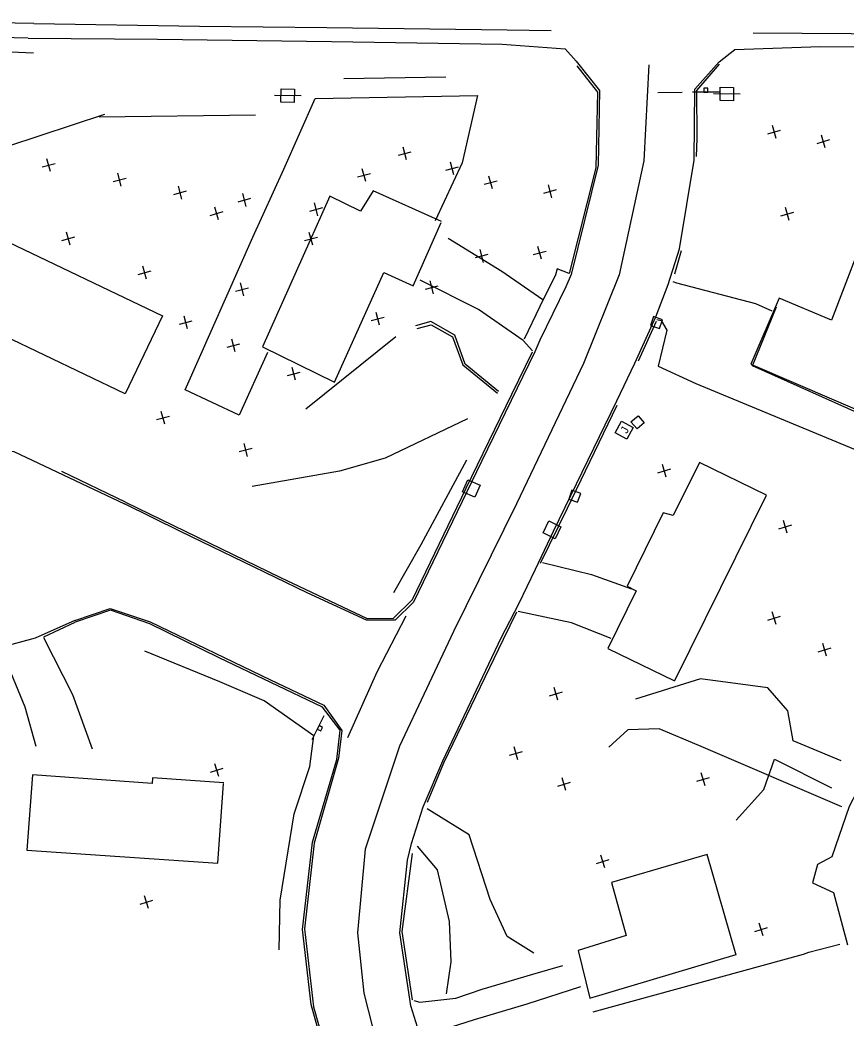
# Model space of a CAD drawing. Extents: x 4711259 to 4716401, y 890074 to 892728.
# Drawn here: x 4713612.2 to 4713922, y 890972 to 891346.1 of the extents above; entities that cross this region are included whole.
import ezdxf

# ---------------------------------------------------------------- set-up
doc = ezdxf.new("R2010")
doc.units = 0
for name, color, linetype in [('E_HY_STORM_Inlet', 7, 'Continuous'), ('E_RDWY_PHOTOG_Eave', 7, 'Continuous'), ('E_RDWY_PHOTOG_Fence', 7, 'Continuous'), ('E_RDWY_ROAD_Approach', 7, 'Continuous'), ('E_RDWY_ROAD_Curb', 7, 'Continuous'), ('E_RDWY_ROAD_EdgeAsph', 7, 'Continuous'), ('E_RDWY_ROAD_EdgeGravel', 7, 'Continuous'), ('E_RDWY_ROAD_Mailbox', 7, 'Continuous'), ('E_RDWY_ROAD_Sidewalk', 7, 'Continuous'), ('E_RDWY_ROAD_Striping', 7, 'Continuous'), ('E_RDWY_ROAD_TBofCurb', 7, 'Continuous'), ('E_TERR_DTM_BrkLines', 7, 'Continuous'), ('E_TERR_DTM_RandomPt', 7, 'Continuous'), ('E_TRAF_SIGN_PublicSign', 7, 'Continuous'), ('E_UTIL_COMM_General', 7, 'Continuous'), ('E_UTIL_ELEC_GENERAL', 7, 'Continuous'), ('E_UTIL_ELEC_POLE', 7, 'Continuous')]:
    doc.layers.add(name, color=color, linetype=linetype)

msp = doc.modelspace()

# ---------------------------------------------------------------- linework, layer by layer
at = {"layer": 'E_HY_STORM_Inlet'}
for p, q in [((4713781.5, 891170.44), (4713781.5, 891170.44)), ((4713811.71, 891154.94), (4713811.71, 891154.94))]:
    msp.add_line(p, q, dxfattribs=at)
for points in [[(4713784.8, 891171.73), (4713782.79, 891167.15), (4713778.21, 891169.16), (4713780.22, 891173.74)], [(4713815.05, 891156.09), (4713812.86, 891151.6), (4713808.37, 891153.79), (4713810.56, 891158.28)]]:
    msp.add_lwpolyline(points, close=True, dxfattribs=at)
at = {"layer": 'E_RDWY_PHOTOG_Eave'}
for points in [[(4713770.26, 891270.48), (4713744.67, 891282.04), (4713739.98, 891274.39), (4713728.39, 891280.01), (4713703.14, 891223.52), (4713730.13, 891210.37), (4713748.66, 891251.38), (4713759.64, 891246.46), (4713770.2, 891270.2)], [(4713934.33, 891196.53), (4713960.95, 891259.55), (4713931.47, 891272.28), (4713916.57, 891233.61), (4713896.9, 891241.74), (4713886.26, 891217.06), (4713934.29, 891196.47)], [(4713857.75, 891098.46), (4713892.22, 891167.97), (4713867.04, 891180.17), (4713857.2, 891160.28), (4713853.47, 891161.32), (4713839.9, 891133.88), (4713843.25, 891132.13), (4713832.68, 891110.45), (4713857.61, 891098.37)], [(4713688.73, 891060.1), (4713661.94, 891061.99), (4713661.79, 891059.93), (4713616.92, 891063.17), (4713614.83, 891034.87), (4713686.4, 891029.98), (4713688.58, 891059.91)], [(4713880.83, 890995.6), (4713869.91, 891033.23), (4713834, 891022.8), (4713839.58, 891002.9), (4713821.55, 890997.33), (4713825.88, 890979.41), (4713880.76, 890995.83)]]:
    msp.add_lwpolyline(points, dxfattribs=at)
msp.add_lwpolyline([(4713651.67, 891205.9), (4713591.05, 891234.94), (4713605.06, 891264.19), (4713665.68, 891235.14)], close=True, dxfattribs=at)
at = {"layer": 'E_RDWY_PHOTOG_Fence'}
for points in [[(4713705.08, 891221.42), (4713694.43, 891197.99), (4713674.22, 891207.45), (4713699.58, 891264.71), (4713711.22, 891290.12), (4713722.98, 891316.63), (4713783.79, 891317.77), (4713778.07, 891292.53), (4713767.89, 891270.76)], [(4713920.39, 891051.18), (4713866.81, 891074.09), (4713851.95, 891080.37), (4713840.15, 891079.97), (4713833.04, 891073.53)], [(4713827.17, 890974.29), (4713905.99, 890995.98), (4713908.03, 890996.62), (4713919.65, 890999.64)]]:
    msp.add_lwpolyline(points, dxfattribs=at)
at = {"layer": 'E_RDWY_ROAD_Approach'}
for points in [[(4713772.8, 891264.33), (4713792.93, 891251.96), (4713808.27, 891241.25)], [(4713804.47, 891222.03), (4713800.9, 891225.9), (4713784.12, 891237.6), (4713762.35, 891248.54)], [(4713857.1, 891248.08), (4713858.4, 891247.54), (4713888.03, 891239.82), (4713894.19, 891237.03)], [(4713931.07, 891196.74), (4713886.94, 891216.45), (4713895.86, 891238.55)], [(4713851.09, 891233.83), (4713852.72, 891233.38), (4713854.79, 891229.83), (4713851.5, 891216.25), (4713865.66, 891209.81), (4713926.93, 891184.43), (4713931.12, 891196.58)], [(4713808.18, 891142.66), (4713826.51, 891138.25), (4713841.53, 891132.9)], [(4713833.91, 891114.29), (4713819.02, 891120.17), (4713799.03, 891124.38)], [(4713639.4, 891072.75), (4713632.04, 891093.18), (4713621.12, 891114.5)], [(4713605.32, 891109.86), (4713614.07, 891088.61), (4713618.17, 891073.87)], [(4713759.91, 890978.62), (4713762.11, 890977.91), (4713775.66, 890979.49), (4713785.53, 890982.83), (4713804.53, 890988.41), (4713815.85, 890991.69)], [(4713822.42, 890983.73), (4713802.31, 890977.23), (4713782.55, 890971.3), (4713764.93, 890965.71), (4713763.33, 890965.14)]]:
    msp.add_lwpolyline(points, dxfattribs=at)
at = {"layer": 'E_RDWY_ROAD_Curb'}
for points in [[(4713820.79, 891330.56), (4713829.53, 891319.64), (4713829.1, 891291.65), (4713818.97, 891250.72), (4713816.95, 891246.05), (4713807.22, 891226.01), (4713805.31, 891221.73), (4713785.27, 891180.53)], [(4713812.27, 891154.47), (4713836.08, 891203.37), (4713842.74, 891217.43), (4713850.72, 891234.74), (4713855.24, 891246.87), (4713859.57, 891260.23), (4713865.04, 891293.48), (4713865.31, 891320.17), (4713874.37, 891330.31)], [(4713632.75, 891120.93), (4713617.97, 891114.35), (4713604.44, 891110.69), (4713587.66, 891112.51), (4713571.64, 891123.24), (4713563.52, 891138.46), (4713562.44, 891152.56), (4713565.42, 891163.76), (4713583.14, 891182.06), (4713594.75, 891185.87), (4713609.88, 891184.34), (4713651.39, 891164.73)], [(4713785.27, 891180.53), (4713759.74, 891127.86), (4713752.88, 891121.11), (4713742.14, 891121.05), (4713719.98, 891131.41), (4713672.44, 891154.33), (4713651.39, 891164.73)], [(4713792.72, 891114.44), (4713799.23, 891127.29), (4713805.52, 891140.25), (4713812.27, 891154.47)], [(4713632.75, 891120.93), (4713646.08, 891125.51), (4713661.04, 891120.52), (4713706.14, 891098.8), (4713726.12, 891089.24), (4713732.92, 891079.81), (4713731.68, 891069.33), (4713722.58, 891037.56), (4713718.87, 891005.38), (4713722.24, 890976.18), (4713729.82, 890949.71), (4713731.63, 890945.49), (4713739.82, 890925.16), (4713753.37, 890890.9), (4713766.39, 890858.38), (4713785.05, 890820.46), (4713795.01, 890806.04)], [(4713819.53, 890832.89), (4713799.04, 890872.21), (4713798.23, 890874.51), (4713792.3, 890889.41), (4713775.49, 890931.67), (4713766.89, 890952.83), (4713762.59, 890964.52), (4713758.84, 890976.58), (4713754.63, 891003.97), (4713757.58, 891031.15), (4713759.06, 891037.39), (4713763.46, 891051.1), (4713770.75, 891068.43), (4713792.72, 891114.44)]]:
    msp.add_lwpolyline(points, dxfattribs=at)
at = {"layer": 'E_RDWY_ROAD_EdgeAsph'}
for points in [[(4713615.36, 891339.27), (4713551.94, 891340.74), (4713493.65, 891341.6), (4713437.61, 891342.74), (4713435.93, 891340.25), (4713420.8, 891342.23), (4713393.99, 891341.13), (4713355.17, 891338.55), (4713296.95, 891336.37), (4713247.9, 891334.38)], [(4713615.36, 891339.27), (4713663.82, 891338.83), (4713729.08, 891337.94), (4713793.1, 891337.01), (4713816.66, 891335.3), (4713820.79, 891330.56)], [(4713874.37, 891330.31), (4713880.32, 891335.02), (4713912.29, 891336.09), (4713970.87, 891335.69), (4714017.26, 891335.57), (4714062.02, 891335.32), (4714103.97, 891334.6)]]:
    msp.add_lwpolyline(points, dxfattribs=at)
at = {"layer": 'E_RDWY_ROAD_EdgeGravel'}
for points in [[(4713804.86, 890996.32), (4713794.95, 891002.56), (4713788.54, 891016.43), (4713780.64, 891040.67), (4713764.89, 891050.43)], [(4713761.2, 891036.38), (4713768.63, 891027.54), (4713773.13, 891008.13), (4713773.85, 890993.05), (4713772.01, 890981.05)]]:
    msp.add_lwpolyline(points, dxfattribs=at)
at = {"layer": 'E_RDWY_ROAD_Mailbox'}
for points in [[(4713848.68, 891231.56), (4713851.98, 891230.4), (4713853.14, 891233.7), (4713849.84, 891234.86)], [(4713818.03, 891166.47), (4713821.33, 891165.31), (4713822.49, 891168.61), (4713819.19, 891169.77)]]:
    msp.add_lwpolyline(points, close=True, dxfattribs=at)
at = {"layer": 'E_RDWY_ROAD_Sidewalk'}
msp.add_lwpolyline([(4713818.2, 891251.03), (4713813.7, 891252.73), (4713813, 891250.57), (4713807.2, 891238.7), (4713801.27, 891226.37)], dxfattribs=at)
at = {"layer": 'E_RDWY_ROAD_Striping'}
for points in [[(4713617.48, 891344.68), (4713540.79, 891346.06), (4713469.69, 891346.85), (4713449.38, 891346.86)], [(4713617.48, 891344.68), (4713679.52, 891343.72), (4713727.32, 891343.2), (4713794.97, 891342.38), (4713811.47, 891342.13)], [(4713887.16, 891341.3), (4713942.27, 891340.9), (4714001.89, 891340.83), (4714065.08, 891340.32), (4714120.8, 891339.62), (4714182.86, 891338.54), (4714241.54, 891338.23), (4714273.17, 891337.79)], [(4713848.1, 891329.22), (4713846.22, 891293.23), (4713836.95, 891250.59), (4713823.5, 891217.31), (4713798.38, 891164.65), (4713774.76, 891116.85)], [(4713860.6, 891318.87), (4713851.43, 891318.73)], [(4713754.59, 891073.85), (4713741.63, 891035.28), (4713738.8, 891003.98), (4713741.22, 890981.26), (4713749.08, 890950.43), (4713760.83, 890918.14), (4713781.36, 890868.24), (4713801.22, 890831.56)]]:
    msp.add_lwpolyline(points, dxfattribs=at)
at = {"layer": 'E_RDWY_ROAD_TBofCurb'}
for points in [[(4713818.33, 891251.01), (4713828.33, 891290.58), (4713828.96, 891319.01), (4713821.11, 891328.93)], [(4713874.45, 891329.47), (4713865.91, 891319.59), (4713866.09, 891301.65), (4713865.8, 891294.89)], [(4713860.18, 891259.54), (4713857.71, 891250.79)], [(4713850.74, 891233.1), (4713844.03, 891218.19)], [(4713651.83, 891165.39), (4713709.88, 891137.1), (4713742.4, 891121.77), (4713752.24, 891121.88), (4713759.42, 891128.81), (4713779.6, 891170.56), (4713796.72, 891205.79), (4713804.45, 891221.64)], [(4713836.01, 891201.56), (4713817.38, 891162.91), (4713807.23, 891142.32)], [(4713651.83, 891165.39), (4713627.89, 891176.89)], [(4713729.1, 890949.56), (4713721.38, 890977.01), (4713718.2, 891005.13), (4713721.93, 891037.92), (4713731.01, 891068.92), (4713732.3, 891079.84), (4713725.62, 891088.56), (4713686.9, 891107.05), (4713660.94, 891119.71), (4713646.23, 891124.8), (4713632.95, 891120.39)], [(4713798.44, 891124.11), (4713793.44, 891113.85)], [(4713621.22, 891114.92), (4713632.95, 891120.39)], [(4713793.44, 891113.85), (4713771.07, 891067.56), (4713764.96, 891052.75)], [(4713759.31, 891033.64), (4713755.48, 891004.36), (4713759.27, 890978.78)]]:
    msp.add_lwpolyline(points, dxfattribs=at)
at = {"layer": 'E_TERR_DTM_BrkLines'}
for points in [[(4713302.13, 890810.84), (4713317.61, 890862.47), (4713325.92, 890904.14), (4713338.96, 890949.45), (4713350.11, 890993.6), (4713363.4, 891040.76), (4713373.13, 891091.88), (4713385.24, 891139.46), (4713397.2, 891188.39), (4713412.55, 891244.48), (4713423.84, 891287.6), (4713430.81, 891317.82), (4713434.39, 891333.46), (4713454.87, 891337.03), (4713504.24, 891337.36), (4713549.9, 891337.58), (4713585.94, 891335.12), (4713617.35, 891333.75)], [(4713733.68, 891324.16), (4713771.86, 891324.75)], [(4713586.37, 891263.42), (4713599.12, 891291.36), (4713607.68, 891298.71), (4713644.04, 891310.71)], [(4713641.92, 891309.75), (4713700.58, 891310.48)], [(4714020, 891272.19), (4714008.98, 891240.87), (4714004.61, 891217.46), (4713993.33, 891192.53), (4713975.79, 891153.52), (4713964.29, 891135.2), (4713945.66, 891107.51), (4713943.87, 891100.38), (4713937.54, 891078.76), (4713923.2, 891051.32), (4713916.61, 891032.37), (4713911.24, 891029.56), (4713909.4, 891022.62), (4713917.32, 891019.06), (4713922.48, 890999.46)], [(4713791.63, 891206.84), (4713779.18, 891217.01), (4713775.31, 891227.91), (4713766.34, 891233.03), (4713760.5, 891231.45)], [(4713761.23, 891230.46), (4713766.4, 891231.77), (4713774.41, 891227.28), (4713778.35, 891216.86), (4713791.23, 891206.14)], [(4713719.47, 891200.28), (4713753.21, 891227.4)], [(4713780.09, 891196.51), (4713749.19, 891181.8)], [(4713749.19, 891181.8), (4713732.04, 891176.93), (4713699.33, 891171.26)], [(4713752.43, 891131.48), (4713762.66, 891149.46), (4713779.81, 891181.17)], [(4713756.93, 891122.56), (4713746.1, 891101.59), (4713735.02, 891077.04)], [(4713774.76, 891116.85), (4713754.59, 891073.85)], [(4713709.37, 890997.54), (4713709.78, 891016.16), (4713715.02, 891048.48), (4713720.87, 891066.23), (4713722.4, 891077.74), (4713703.81, 891090.87), (4713687.2, 891098.03), (4713659.07, 891109.52)], [(4713920.21, 891068.4), (4713902.17, 891075.88), (4713900.16, 891087.18), (4713892.68, 891095.69), (4713867.35, 891099.16), (4713843.05, 891091.53)], [(4713880.77, 891046.15), (4713891.1, 891057.7), (4713895.11, 891068.96), (4713916.48, 891058.21)]]:
    msp.add_lwpolyline(points, dxfattribs=at)
at = {"layer": 'E_TERR_DTM_RandomPt'}
for p, q in [((4713892.69, 891303.33), (4713897.47, 891304.78)), ((4713895.8, 891301.66), (4713894.36, 891306.45)), ((4713911.1, 891299.81), (4713915.88, 891301.26)), ((4713914.21, 891298.14), (4713912.77, 891302.93)), ((4713757.17, 891293.62), (4713755.88, 891298.44)), ((4713623.63, 891289.23), (4713622.34, 891294.06)), ((4713754.11, 891295.38), (4713758.94, 891296.68)), ((4713620.57, 891291), (4713625.4, 891292.29)), ((4713741.88, 891285.48), (4713740.58, 891290.31)), ((4713771.86, 891289.76), (4713776.69, 891291.06)), ((4713774.93, 891287.99), (4713773.63, 891292.82)), ((4713647.16, 891285.53), (4713651.99, 891286.82)), ((4713650.23, 891283.76), (4713648.93, 891288.59)), ((4713738.81, 891287.25), (4713743.64, 891288.55)), ((4713786.31, 891284.52), (4713791.14, 891285.81)), ((4713789.37, 891282.75), (4713788.08, 891287.58)), ((4713669.9, 891280.69), (4713674.73, 891281.98)), ((4713672.96, 891278.92), (4713671.67, 891283.75)), ((4713808.62, 891281.18), (4713813.45, 891282.47)), ((4713811.68, 891279.41), (4713810.39, 891284.24)), ((4713694.02, 891277.95), (4713698.85, 891279.25)), ((4713697.08, 891276.19), (4713695.78, 891281.02)), ((4713686.72, 891271.14), (4713685.28, 891275.93)), ((4713720.91, 891274.45), (4713725.74, 891275.74)), ((4713723.97, 891272.68), (4713722.68, 891277.51)), ((4713900.68, 891270.96), (4713899.23, 891275.75)), ((4713683.61, 891272.81), (4713688.39, 891274.26)), ((4713897.56, 891272.63), (4713902.35, 891274.08)), ((4713627.94, 891263.45), (4713632.77, 891264.74)), ((4713631.01, 891261.68), (4713629.71, 891266.51)), ((4713718.93, 891263.37), (4713723.76, 891264.67)), ((4713721.99, 891261.61), (4713720.69, 891266.44)), ((4713786.07, 891255.22), (4713784.78, 891260.05)), ((4713804.67, 891258.15), (4713809.5, 891259.45)), ((4713807.73, 891256.38), (4713806.43, 891261.21)), ((4713783.01, 891256.99), (4713787.84, 891258.28)), ((4713656.6, 891250.7), (4713661.43, 891252)), ((4713659.66, 891248.94), (4713658.36, 891253.77)), ((4713767.3, 891243.4), (4713766.01, 891248.23)), ((4713693.11, 891244.43), (4713697.94, 891245.72)), ((4713696.18, 891242.66), (4713694.88, 891247.49)), ((4713764.24, 891245.17), (4713769.07, 891246.46)), ((4713672, 891232.02), (4713676.83, 891233.31)), ((4713675.06, 891230.25), (4713673.76, 891235.08)), ((4713743.97, 891233.4), (4713748.8, 891234.7)), ((4713747.04, 891231.64), (4713745.74, 891236.47)), ((4713692.95, 891221.62), (4713691.65, 891226.45)), ((4713689.88, 891223.39), (4713694.71, 891224.68)), ((4713715.58, 891211.01), (4713714.29, 891215.84)), ((4713712.52, 891212.78), (4713717.35, 891214.07)), ((4713663.46, 891196.29), (4713668.29, 891197.59)), ((4713666.52, 891194.52), (4713665.23, 891199.35)), ((4713694.48, 891184.28), (4713699.31, 891185.57)), ((4713697.54, 891182.51), (4713696.25, 891187.34)), ((4713851.46, 891176.33), (4713856.24, 891177.77)), ((4713854.57, 891174.66), (4713853.13, 891179.44)), ((4713899.94, 891153.68), (4713898.49, 891158.47)), ((4713896.82, 891155.35), (4713901.61, 891156.8)), ((4713892.65, 891121.13), (4713897.44, 891122.58)), ((4713895.77, 891119.46), (4713894.32, 891124.25)), ((4713911.57, 891109.24), (4713916.36, 891110.68)), ((4713914.69, 891107.57), (4713913.24, 891112.35)), ((4713813.95, 891091.1), (4713812.5, 891095.89)), ((4713810.83, 891092.77), (4713815.62, 891094.22)), ((4713798.95, 891068.81), (4713797.5, 891073.59)), ((4713795.83, 891070.48), (4713800.62, 891071.92)), ((4713683.69, 891064.14), (4713688.48, 891065.59)), ((4713686.8, 891062.47), (4713685.36, 891067.26)), ((4713816.97, 891057.26), (4713815.53, 891062.05)), ((4713866.05, 891060.72), (4713870.84, 891062.16)), ((4713869.17, 891059.05), (4713867.72, 891063.83)), ((4713813.86, 891058.93), (4713818.64, 891060.37)), ((4713828.37, 891029.95), (4713833.16, 891031.4)), ((4713831.49, 891028.28), (4713830.04, 891033.07)), ((4713660.41, 891013.02), (4713658.96, 891017.81)), ((4713657.29, 891014.69), (4713662.08, 891016.14)), ((4713887.8, 891004.48), (4713892.59, 891005.92)), ((4713890.92, 891002.81), (4713889.47, 891007.59))]:
    msp.add_line(p, q, dxfattribs=at)
at = {"layer": 'E_TRAF_SIGN_PublicSign'}
for p, q in [((4713869.45, 891319.74), (4713869.45, 891319.74)), ((4713874.44, 891318.94), (4713864.44, 891319.04)), ((4713721.82, 891076.43), (4713726.28, 891085.38)), ((4713724.72, 891080.57), (4713724.72, 891080.57))]:
    msp.add_line(p, q, dxfattribs=at)
for points in [[(4713870.19, 891318.98), (4713870.21, 891320.48), (4713868.71, 891320.5), (4713868.69, 891319)], [(4713723.71, 891080.23), (4713725.06, 891079.57), (4713725.72, 891080.91), (4713724.38, 891081.58)]]:
    msp.add_lwpolyline(points, close=True, dxfattribs=at)
at = {"layer": 'E_UTIL_COMM_General'}
msp.add_lwpolyline([(4713843.65, 891192.79), (4713841.34, 891195.42), (4713843.98, 891197.73), (4713846.28, 891195.09)], close=True, dxfattribs=at)
at = {"layer": 'E_UTIL_ELEC_GENERAL'}
msp.add_lwpolyline([(4713842.2, 891193.33), (4713839.83, 891188.93), (4713835.43, 891191.3), (4713837.8, 891195.7)], close=True, dxfattribs=at)
at = {"layer": 'E_UTIL_ELEC_POLE'}
for p, q in [((4713717.64, 891317.63), (4713707.64, 891317.79)), ((4713882.3, 891318.27), (4713872.3, 891318.35))]:
    msp.add_line(p, q, dxfattribs=at)
for points in [[(4713715.1, 891315.17), (4713710.1, 891315.25), (4713710.17, 891320.25), (4713715.17, 891320.17)], [(4713879.78, 891315.79), (4713874.78, 891315.83), (4713874.83, 891320.83), (4713879.83, 891320.79)]]:
    msp.add_lwpolyline(points, close=True, dxfattribs=at)

# ---------------------------------------------------------------- texts
at = {"layer": 'E_UTIL_ELEC_GENERAL'}
msp.add_text('J', height=3, rotation=61.6837, dxfattribs=at).set_placement((4713839.8, 891190.82))

doc.saveas('drawing.dxf')
